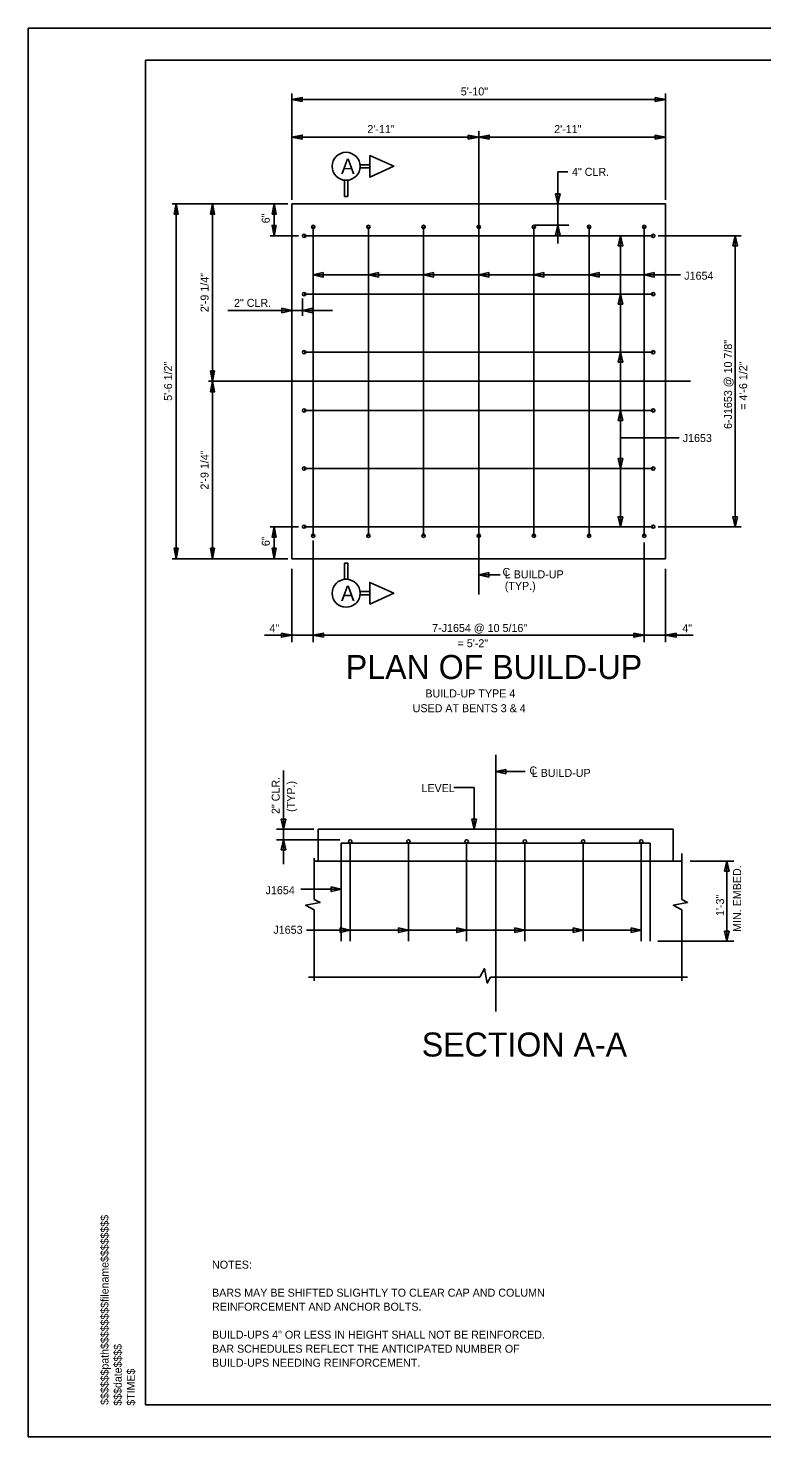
# Model space of a CAD drawing. Extents: x -133.1 to -97, y -110.1 to -88.1.
# Drawn here: x -133.14 to -121.69, y -110.1 to -88.1 of the extents above; entities that cross this region are included whole.
import ezdxf

# ---------------------------------------------------------------- set-up
doc = ezdxf.new("R2010")
doc.units = 0
for name, color, linetype in [('BR_AUTO DIMENSION', 7, 'Continuous'), ('BR_BORDER LINES', 7, 'Continuous'), ('BR_CENTER LINES', 7, 'Continuous'), ('BR_CONCRETE', 7, 'Continuous'), ('BR_REBAR', 7, 'Continuous'), ('BR_TEXT', 7, 'Continuous'), ('Default', 7, 'Continuous'), ('Level 31', 7, 'Continuous'), ('RD_SHT_ID', 7, 'Continuous')]:
    doc.layers.add(name, color=color, linetype=linetype)

msp = doc.modelspace()

# ---------------------------------------------------------------- linework, layer by layer
at = {"layer": 'BR_AUTO DIMENSION'}
for p, q in [((-129.026, -90.784), (-129.026, -89.123)), ((-129.026, -89.216), (-123.193, -89.216)), ((-123.193, -90.784), (-123.193, -89.123)), ((-126.11, -90.61), (-126.11, -89.709)), ((-129.026, -89.803), (-126.11, -89.803)), ((-123.193, -89.803), (-126.11, -89.803)), ((-124.873, -91.468), (-124.873, -90.347)), ((-124.719, -90.347), (-124.873, -90.347)), ((-129.089, -90.847), (-130.895, -90.847)), ((-130.832, -96.388), (-130.832, -90.847)), ((-130.264, -90.847), (-130.264, -93.618)), ((-129.304, -90.847), (-129.304, -91.347)), ((-129.026, -90.847), (-129.026, -90.847)), ((-125.233, -91.18), (-124.701, -91.18)), ((-128.925, -91.347), (-129.366, -91.347)), ((-123.899, -91.347), (-123.899, -95.888)), ((-123.308, -91.347), (-122.016, -91.347)), ((-122.108, -91.347), (-122.108, -95.888)), ((-128.693, -91.953), (-122.961, -91.953)), ((-128.86, -92.327), (-128.86, -92.597)), ((-128.391, -92.512), (-130.025, -92.512)), ((-129.627, -93.618), (-130.326, -93.618)), ((-130.264, -96.388), (-130.264, -93.618)), ((-123.899, -94.501), (-122.982, -94.501)), ((-128.925, -95.888), (-129.366, -95.888)), ((-129.304, -96.388), (-129.304, -95.888)), ((-123.308, -95.888), (-122.016, -95.888)), ((-128.693, -96.105), (-128.693, -97.69)), ((-123.526, -96.137), (-123.526, -97.69)), ((-129.089, -96.388), (-130.895, -96.388)), ((-129.026, -96.388), (-129.026, -96.388)), ((-129.026, -96.544), (-129.026, -97.69)), ((-123.193, -96.544), (-123.193, -97.69)), ((-126.11, -96.64), (-125.773, -96.64)), ((-128.693, -97.584), (-129.455, -97.584)), ((-128.693, -97.584), (-123.526, -97.584)), ((-123.526, -97.584), (-122.764, -97.584)), ((-129.156, -99.694), (-129.156, -101.159)), ((-125.844, -99.714), (-125.384, -99.714)), ((-126.496, -99.961), (-126.18, -99.961)), ((-126.18, -99.961), (-126.18, -100.611)), ((-128.684, -100.611), (-129.265, -100.611)), ((-128.278, -100.777), (-129.265, -100.777)), ((-122.811, -101.112), (-122.131, -101.112)), ((-122.237, -101.112), (-122.237, -102.362)), ((-128.255, -101.55), (-128.887, -101.55)), ((-123.573, -102.19), (-128.795, -102.19)), ((-128.115, -102.19), (-128.195, -102.19)), ((-127.206, -102.19), (-127.287, -102.19)), ((-126.298, -102.19), (-126.378, -102.19)), ((-125.39, -102.19), (-125.47, -102.19)), ((-124.481, -102.19), (-124.562, -102.19)), ((-123.573, -102.19), (-123.653, -102.19)), ((-123.312, -102.362), (-122.131, -102.362))]:
    msp.add_line(p, q, dxfattribs=at)
for points in [[(-128.864, -89.247), (-129.026, -89.216), (-128.864, -89.185)], [(-123.356, -89.185), (-123.193, -89.216), (-123.356, -89.247)], [(-128.864, -89.835), (-129.026, -89.803), (-128.864, -89.772)], [(-126.272, -89.772), (-126.11, -89.803), (-126.272, -89.835)], [(-125.947, -89.835), (-126.11, -89.803), (-125.947, -89.772)], [(-123.356, -89.772), (-123.193, -89.803), (-123.356, -89.835)], [(-130.863, -91.009), (-130.832, -90.847), (-130.801, -91.009)], [(-130.295, -91.009), (-130.264, -90.847), (-130.233, -91.009)], [(-129.335, -91.009), (-129.304, -90.847), (-129.272, -91.009)], [(-124.837, -90.691), (-124.873, -90.847), (-124.909, -90.691)], [(-129.272, -91.184), (-129.304, -91.347), (-129.335, -91.184)], [(-124.909, -91.336), (-124.873, -91.18), (-124.837, -91.336)], [(-123.935, -91.503), (-123.899, -91.347), (-123.863, -91.503)], [(-122.144, -91.503), (-122.108, -91.347), (-122.072, -91.503)], [(-128.537, -91.917), (-128.693, -91.953), (-128.537, -91.989)], [(-127.676, -91.917), (-127.832, -91.953), (-127.676, -91.989)], [(-126.815, -91.917), (-126.971, -91.953), (-126.815, -91.989)], [(-125.954, -91.917), (-126.11, -91.953), (-125.954, -91.989)], [(-125.093, -91.917), (-125.249, -91.953), (-125.093, -91.989)], [(-124.231, -91.917), (-124.387, -91.953), (-124.231, -91.989)], [(-123.37, -91.917), (-123.526, -91.953), (-123.37, -91.989)], [(-123.935, -92.411), (-123.899, -92.255), (-123.863, -92.411)], [(-129.182, -92.548), (-129.026, -92.512), (-129.182, -92.476)], [(-128.704, -92.476), (-128.86, -92.512), (-128.704, -92.548)], [(-123.935, -93.319), (-123.899, -93.163), (-123.863, -93.319)], [(-130.233, -93.455), (-130.264, -93.618), (-130.295, -93.455)], [(-130.295, -93.78), (-130.264, -93.618), (-130.233, -93.78)], [(-123.935, -94.228), (-123.899, -94.072), (-123.863, -94.228)], [(-123.863, -94.824), (-123.899, -94.98), (-123.935, -94.824)], [(-129.272, -96.051), (-129.304, -95.888), (-129.335, -96.051)], [(-123.863, -95.732), (-123.899, -95.888), (-123.935, -95.732)], [(-122.072, -95.732), (-122.108, -95.888), (-122.144, -95.732)], [(-130.801, -96.226), (-130.832, -96.388), (-130.863, -96.226)], [(-130.233, -96.226), (-130.264, -96.388), (-130.295, -96.226)], [(-129.335, -96.226), (-129.304, -96.388), (-129.272, -96.226)], [(-125.954, -96.676), (-126.11, -96.64), (-125.954, -96.604)], [(-129.189, -97.553), (-129.026, -97.584), (-129.189, -97.615)], [(-128.531, -97.615), (-128.693, -97.584), (-128.531, -97.553)], [(-123.689, -97.553), (-123.526, -97.584), (-123.689, -97.615)], [(-123.031, -97.553), (-123.193, -97.584), (-123.031, -97.615)], [(-125.688, -99.75), (-125.844, -99.714), (-125.688, -99.678)], [(-129.12, -100.455), (-129.156, -100.611), (-129.192, -100.455)], [(-126.144, -100.455), (-126.18, -100.611), (-126.216, -100.455)], [(-129.192, -100.933), (-129.156, -100.777), (-129.12, -100.933)], [(-122.273, -101.268), (-122.237, -101.112), (-122.201, -101.268)], [(-128.411, -101.514), (-128.255, -101.55), (-128.411, -101.586)], [(-128.271, -102.154), (-128.115, -102.19), (-128.271, -102.226)], [(-127.362, -102.154), (-127.206, -102.19), (-127.362, -102.226)], [(-126.454, -102.154), (-126.298, -102.19), (-126.454, -102.226)], [(-125.546, -102.154), (-125.39, -102.19), (-125.546, -102.226)], [(-124.637, -102.154), (-124.481, -102.19), (-124.637, -102.226)], [(-123.729, -102.154), (-123.573, -102.19), (-123.729, -102.226)], [(-122.201, -102.206), (-122.237, -102.362), (-122.273, -102.206)]]:
    msp.add_lwpolyline(points, close=True, dxfattribs=at)
at = {"layer": 'BR_BORDER LINES'}
for p, q in [((-97.642, -88.603), (-131.308, -88.603)), ((-131.308, -109.603), (-131.308, -88.603)), ((-131.308, -109.603), (-97.642, -109.603))]:
    msp.add_line(p, q, dxfattribs=at)
at = {"layer": 'BR_CENTER LINES'}
for p, q in [((-126.11, -96.946), (-126.11, -90.223)), ((-122.807, -93.618), (-129.662, -93.618)), ((-125.844, -99.453), (-125.844, -103.461))]:
    msp.add_line(p, q, dxfattribs=at)
at = {"layer": 'BR_CONCRETE'}
for p, q in [((-129.026, -90.847), (-129.026, -96.388)), ((-123.193, -90.847), (-129.026, -90.847)), ((-123.193, -90.847), (-123.193, -96.388)), ((-123.193, -96.388), (-129.026, -96.388)), ((-128.615, -100.611), (-128.615, -101.112)), ((-128.615, -100.611), (-123.073, -100.611)), ((-123.073, -100.611), (-123.073, -101.112)), ((-128.676, -101.112), (-122.94, -101.112))]:
    msp.add_line(p, q, dxfattribs=at)
at = {"layer": 'BR_REBAR'}
for p, q in [((-128.693, -96.029), (-128.693, -91.206)), ((-127.832, -96.029), (-127.832, -91.206)), ((-126.971, -96.029), (-126.971, -91.206)), ((-126.11, -96.029), (-126.11, -91.206)), ((-125.249, -96.029), (-125.249, -91.206)), ((-124.387, -96.029), (-124.387, -91.206)), ((-123.526, -96.029), (-123.526, -91.206)), ((-128.834, -91.347), (-123.386, -91.347)), ((-128.834, -92.255), (-123.386, -92.255)), ((-128.834, -93.163), (-123.386, -93.163)), ((-128.834, -94.072), (-123.386, -94.072)), ((-128.834, -94.98), (-123.386, -94.98)), ((-128.834, -95.888), (-123.386, -95.888)), ((-128.255, -100.829), (-128.255, -102.362)), ((-123.432, -100.829), (-128.255, -100.829)), ((-128.115, -102.362), (-128.115, -100.829)), ((-127.206, -102.362), (-127.206, -100.829)), ((-126.298, -102.362), (-126.298, -100.829)), ((-125.39, -102.362), (-125.39, -100.829)), ((-124.481, -102.362), (-124.481, -100.829)), ((-123.573, -102.362), (-123.573, -100.829)), ((-123.432, -100.829), (-123.432, -102.362))]:
    msp.add_line(p, q, dxfattribs=at)
for centre, radius in [((-128.693, -91.206), 0.026), ((-127.832, -91.206), 0.026), ((-126.971, -91.206), 0.026), ((-126.11, -91.206), 0.026), ((-125.249, -91.206), 0.026), ((-124.387, -91.206), 0.026), ((-123.526, -91.206), 0.026), ((-128.834, -91.347), 0.026), ((-123.386, -91.347), 0.026), ((-128.834, -92.255), 0.026), ((-123.386, -92.255), 0.026), ((-128.834, -93.163), 0.026), ((-123.386, -93.163), 0.026), ((-128.834, -94.072), 0.026), ((-123.386, -94.072), 0.026), ((-128.834, -94.98), 0.026), ((-123.386, -94.98), 0.026), ((-128.834, -95.888), 0.026), ((-123.386, -95.888), 0.026), ((-128.693, -96.029), 0.026), ((-127.832, -96.029), 0.026), ((-126.971, -96.029), 0.026), ((-126.11, -96.029), 0.026), ((-125.249, -96.029), 0.026), ((-124.387, -96.029), 0.026), ((-123.526, -96.029), 0.026), ((-128.115, -100.803), 0.0261), ((-127.206, -100.803), 0.0261), ((-126.298, -100.803), 0.0261), ((-125.39, -100.803), 0.0261), ((-124.481, -100.803), 0.0261), ((-123.573, -100.803), 0.0261)]:
    msp.add_circle(centre, radius, dxfattribs=at)
at = {"layer": 'BR_TEXT'}
for points in [[(-127.81, -90.091), (-127.435, -90.26), (-127.81, -90.429)], [(-127.961, -90.285), (-127.81, -90.285), (-127.81, -90.235), (-127.961, -90.235)], [(-128.204, -90.729), (-128.154, -90.729), (-128.154, -90.479), (-128.204, -90.479)], [(-128.204, -96.458), (-128.154, -96.458), (-128.154, -96.709), (-128.204, -96.709)], [(-127.81, -97.096), (-127.435, -96.928), (-127.81, -96.759)], [(-127.961, -96.903), (-127.81, -96.903), (-127.81, -96.953), (-127.961, -96.953)]]:
    msp.add_lwpolyline(points, close=True, dxfattribs=at)
for centre in [(-128.179, -90.26), (-128.179, -96.928)]:
    msp.add_circle(centre, 0.219, dxfattribs=at)
at = {"layer": 'Default'}
for p, q in [((-128.676, -101.709), (-128.676, -101.065)), ((-122.94, -101.709), (-122.94, -100.991)), ((-128.676, -102.982), (-128.676, -101.871)), ((-122.94, -102.982), (-122.94, -101.871)), ((-128.765, -102.924), (-126.09, -102.924)), ((-125.928, -102.924), (-122.852, -102.924))]:
    msp.add_line(p, q, dxfattribs=at)
for points in [[(-128.676, -101.709), (-128.585, -101.758), (-128.811, -101.801), (-128.676, -101.871)], [(-122.94, -101.709), (-122.849, -101.758), (-123.075, -101.801), (-122.94, -101.871)], [(-125.928, -102.924), (-125.977, -103.015), (-126.02, -102.789), (-126.09, -102.924)]]:
    msp.add_lwpolyline(points, dxfattribs=at)
at = {"layer": 'Level 31'}
msp.add_lwpolyline([(-133.141, -110.103), (-97.141, -110.103), (-97.141, -88.103), (-133.141, -88.103)], close=True, dxfattribs=at)

# ---------------------------------------------------------------- texts
at = {"layer": 'BR_AUTO DIMENSION'}
for s, p in [('5\'-10"', (-126.39, -89.153)), ('2\'-11"', (-127.848, -89.741)), ('2\'-11"', (-124.932, -89.741)), ('4" CLR.', (-124.654, -90.409)), ('J1654', (-122.902, -92.031)), ('2" CLR.', (-129.929, -92.456)), ('J1653', (-122.926, -94.566)), ('C', (-125.738, -96.658)), ('L BUILD-UP', (-125.703, -96.695)), ('(TYP.)', (-125.703, -96.875)), ('4"', (-129.375, -97.536)), ('7-J1654 @ 10 5/16"', (-126.837, -97.533)), ('4"', (-122.933, -97.536)), ('= 5\'-2"', (-126.44, -97.771)), ('BUILD-UP TYPE 4', (-126.942, -98.555)), ('USED AT BENTS 3 & 4', (-127.141, -98.786)), ('C', (-125.318, -99.759)), ('L BUILD-UP', (-125.283, -99.796)), ('NOTES:', (-130.272, -107.476)), ('BARS MAY BE SHIFTED SLIGHTLY TO CLEAR CAP AND COLUMN', (-130.272, -107.914)), ('REINFORCEMENT AND ANCHOR BOLTS.', (-130.272, -108.133)), ('BUILD-UPS 4" OR LESS IN HEIGHT SHALL NOT BE REINFORCED.', (-130.272, -108.57)), ('BAR SCHEDULES REFLECT THE ANTICIPATED NUMBER OF', (-130.272, -108.789)), ('BUILD-UPS NEEDING REINFORCEMENT.', (-130.272, -109.008))]:
    msp.add_text(s, height=0.125, dxfattribs=at).set_placement(p)
for s, rotation, p in [('6"', 90, (-129.371, -91.15)), ('2\'-9 1/4"', 90, (-130.326, -92.538)), ('6-J1653 @ 10 7/8"', 90, (-122.157, -94.362)), ('5\'-6 1/2"', 90, (-130.895, -93.923)), ('= 4\'-6 1/2"', 90, (-121.92, -94.064)), ('2\'-9 1/4"', 90, (-130.326, -95.309)), ('6"', 90, (-129.371, -96.192)), ('2" CLR.', 90, (-129.216, -100.376)), ('(TYP.)', 90, (-128.978, -100.343)), ('LEVEL', 360, (-127.004, -100.034)), ('MIN. EMBED.', 90, (-122.015, -102.217)), ('J1654', 360, (-129.436, -101.628)), ('1\'-3" ', 90, (-122.281, -101.969)), ('J1653', 360, (-129.314, -102.246))]:
    msp.add_text(s, height=0.125, rotation=rotation, dxfattribs=at).set_placement(p)
at = {"layer": 'BR_TEXT'}
for s, height, p in [('A', 0.24, (-128.26, -90.38)), ('A', 0.24, (-128.26, -97.048)), ('PLAN OF BUILD-UP', 0.375, (-128.184, -98.267))]:
    msp.add_text(s, height=height, dxfattribs=at).set_placement(p)
msp.add_text('SECTION A-A', height=0.375, rotation=360, dxfattribs=at).set_placement((-126.999, -104.163))
at = {"layer": 'RD_SHT_ID'}
for s, height, p in [('$$$$$$path$$$$$$$$filename$$$$$$$$', 0.12347, (-131.887, -109.603)), ('$$$date$$$$', 0.12347, (-131.682, -109.616)), ('$TIME$', 0.1235, (-131.477, -109.616))]:
    msp.add_text(s, height=height, rotation=90, dxfattribs=at).set_placement(p)

doc.saveas('drawing.dxf')
